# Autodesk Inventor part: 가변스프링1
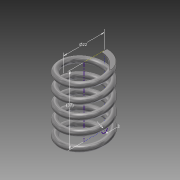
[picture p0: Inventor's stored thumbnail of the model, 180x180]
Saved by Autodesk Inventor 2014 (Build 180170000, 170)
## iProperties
Created: 2015-02
Part Number: 가변스프링1
Material: 강철, 탄소
Document SubType Name: Modeling
Designer: basic
Density: 7.87 g/cm^3
Appearance: 반연마
Mass: 18.9154 g
Surface Area: 32.5802 cm^2
Volume: 2.40348 cm^3
Author: basic
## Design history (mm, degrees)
sketch "스케치1"
  geometry: L1 (0, 0)-(11, 0); L2 (11, 0)-(11, 40.095); L3 (11, 40.095)-(0, 40.095); L4 (0, 40.095)-(0, 0); C1 r 1.5 at (11, 0)
  constraints: 8 end point, 2 parallel, 1 centre point, 1 coincident, 1 horizontal, 1 perpendicular
  dimensions: "d0" = 22 diameter of L2 L4; "d1" = 40.0955 distance of L3.end L1.start (derived); "d2" = 3 diameter of C1
feature "코일1" sketch "스케치1" pitch "d3" = 10; turns "d5" = 5; dims "d4" = 40.0955 (= d1), "d6" = 0, angle "d7" = 90 deg, angle "d8" = 90 deg, "d9" = 0, "d10" = 0
sketch "스케치2"
  geometry: L1 (0, 12.5)-(0, 9.5) reference; L2 (0, 12.5)-(0, 9.5) reference; 1 further point
  constraints: 2 vertical alignment
extrude "돌출1" cut sketch "스케치2" stored distance "d11" = 10; taper "d12" = 0 deg
node "작업 평면1"
sketch "스케치3"
  geometry: L1 (1.5, 0)-(-1.5, 0) reference; 1 further point
  constraints: 1 horizontal alignment
extrude "돌출2" cut sketch "스케치3" stored distance "d14" = 10; taper "d15" = 0 deg
node "솔리드1"
node "절단 모서리 투영1"
node "절단 모서리 투영2"
node "절단 모서리 투영3"
other parameters: "d13" = 0
